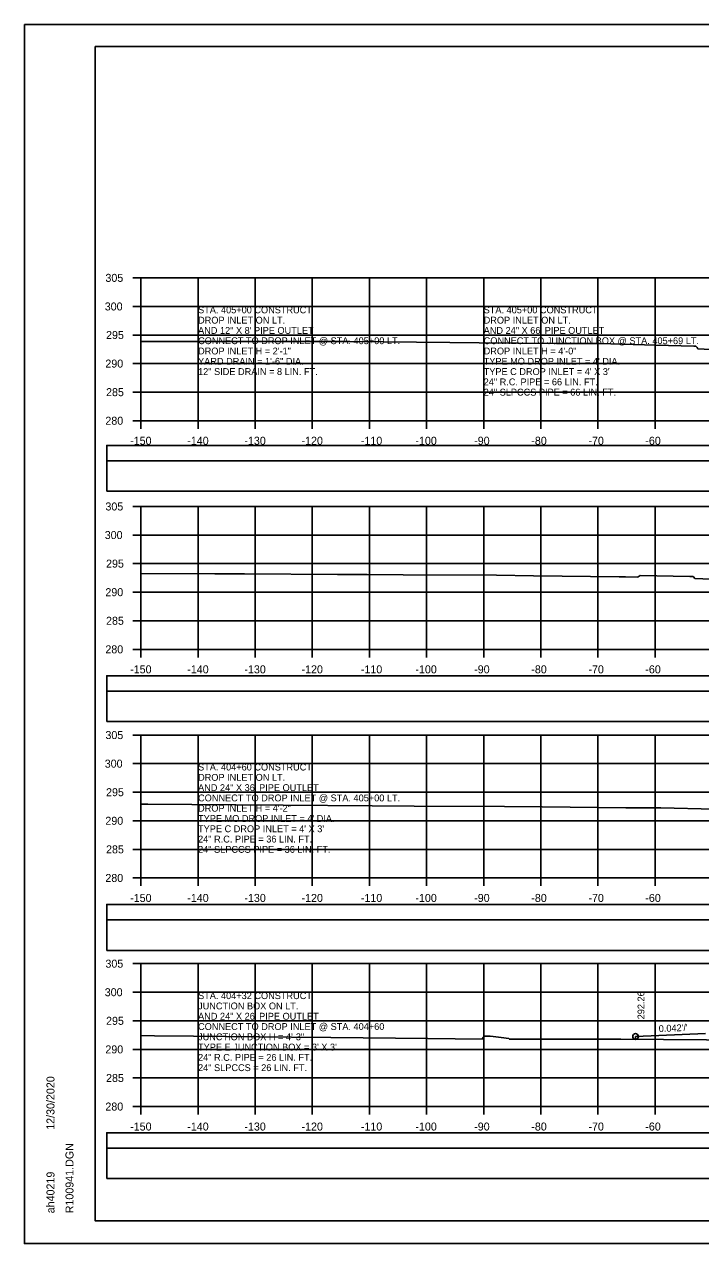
# Model space of a CAD drawing. Extents: x 1370538 to 1372872, y 376220 to 381127.
# Drawn here: x 1370538.2 to 1370656.6, y 376860.4 to 377073.8 of the extents above; entities that cross this region are included whole.
import ezdxf

# ---------------------------------------------------------------- set-up
doc = ezdxf.new("R2010")
doc.units = 0
for name, color, linetype in [('R_Border Notes', 7, 'Continuous'), ('R_Border PE', 7, 'Continuous'), ('R_Border Prem', 7, 'Continuous'), ('R_Dimension', 7, 'Continuous'), ('R_Fin Surface', 7, 'Continuous'), ('R_Grid', 7, 'Continuous'), ('R_No Plot', 7, 'Continuous'), ('R_Water Annot', 7, 'Continuous'), ('R_Xsect Elev', 7, 'Continuous'), ('R_Xsect Slope', 7, 'Continuous'), ('T_Detection Zones', 7, 'Continuous')]:
    doc.layers.add(name, color=color, linetype=linetype)

msp = doc.modelspace()

# ---------------------------------------------------------------- linework, layer by layer
at = {"layer": 'R_Border Notes'}
for p, q in [((1370550.61, 377069.89), (1370866.79, 377069.89)), ((1370550.61, 376864.43), (1370550.61, 377069.89)), ((1370550.61, 376864.43), (1370550.61, 376864.43)), ((1370866.79, 376864.43), (1370550.61, 376864.43))]:
    msp.add_line(p, q, dxfattribs=at)
at = {"layer": 'R_Border Prem'}
for p, q in [((1370557.21, 377029.43), (1370558.61, 377029.43)), ((1370558.61, 377004.43), (1370558.61, 377029.43)), ((1370557.21, 377024.43), (1370558.61, 377024.43)), ((1370557.21, 377019.43), (1370558.61, 377019.43)), ((1370557.21, 377014.43), (1370558.61, 377014.43)), ((1370557.21, 377009.43), (1370558.61, 377009.43)), ((1370557.21, 377004.43), (1370558.61, 377004.43)), ((1370558.61, 377004.43), (1370858.61, 377004.43)), ((1370558.61, 377003.03), (1370558.61, 377004.43)), ((1370568.61, 377003.03), (1370568.61, 377004.43)), ((1370578.61, 377003.03), (1370578.61, 377004.43)), ((1370588.61, 377003.03), (1370588.61, 377004.43)), ((1370598.61, 377003.03), (1370598.61, 377004.43)), ((1370608.61, 377003.03), (1370608.61, 377004.43)), ((1370618.61, 377003.03), (1370618.61, 377004.43)), ((1370628.61, 377003.03), (1370628.61, 377004.43)), ((1370638.61, 377003.03), (1370638.61, 377004.43)), ((1370648.61, 377003.03), (1370648.61, 377004.43)), ((1370557.21, 376989.43), (1370558.61, 376989.43)), ((1370558.61, 376964.43), (1370558.61, 376989.43)), ((1370557.21, 376984.43), (1370558.61, 376984.43)), ((1370557.21, 376979.43), (1370558.61, 376979.43)), ((1370557.21, 376974.43), (1370558.61, 376974.43)), ((1370557.21, 376969.43), (1370558.61, 376969.43)), ((1370557.21, 376964.43), (1370558.61, 376964.43)), ((1370558.61, 376964.43), (1370858.61, 376964.43)), ((1370558.61, 376963.03), (1370558.61, 376964.43)), ((1370568.61, 376963.03), (1370568.61, 376964.43)), ((1370578.61, 376963.03), (1370578.61, 376964.43)), ((1370588.61, 376963.03), (1370588.61, 376964.43)), ((1370598.61, 376963.03), (1370598.61, 376964.43)), ((1370608.61, 376963.03), (1370608.61, 376964.43)), ((1370618.61, 376963.03), (1370618.61, 376964.43)), ((1370628.61, 376963.03), (1370628.61, 376964.43)), ((1370638.61, 376963.03), (1370638.61, 376964.43)), ((1370648.61, 376963.03), (1370648.61, 376964.43)), ((1370557.21, 376949.43), (1370558.61, 376949.43)), ((1370558.61, 376924.43), (1370558.61, 376949.43)), ((1370557.21, 376944.43), (1370558.61, 376944.43)), ((1370557.21, 376939.43), (1370558.61, 376939.43)), ((1370557.21, 376934.43), (1370558.61, 376934.43)), ((1370557.21, 376929.43), (1370558.61, 376929.43)), ((1370557.21, 376924.43), (1370558.61, 376924.43)), ((1370558.61, 376924.43), (1370858.61, 376924.43)), ((1370558.61, 376923.03), (1370558.61, 376924.43)), ((1370568.61, 376923.03), (1370568.61, 376924.43)), ((1370578.61, 376923.03), (1370578.61, 376924.43)), ((1370588.61, 376923.03), (1370588.61, 376924.43)), ((1370598.61, 376923.03), (1370598.61, 376924.43)), ((1370608.61, 376923.03), (1370608.61, 376924.43)), ((1370618.61, 376923.03), (1370618.61, 376924.43)), ((1370628.61, 376923.03), (1370628.61, 376924.43)), ((1370638.61, 376923.03), (1370638.61, 376924.43)), ((1370648.61, 376923.03), (1370648.61, 376924.43)), ((1370557.21, 376909.43), (1370558.61, 376909.43)), ((1370558.61, 376884.43), (1370558.61, 376909.43)), ((1370557.21, 376904.43), (1370558.61, 376904.43)), ((1370557.21, 376899.43), (1370558.61, 376899.43)), ((1370557.21, 376894.43), (1370558.61, 376894.43)), ((1370557.21, 376889.43), (1370558.61, 376889.43)), ((1370557.21, 376884.43), (1370558.61, 376884.43)), ((1370558.61, 376884.43), (1370858.61, 376884.43)), ((1370558.61, 376883.03), (1370558.61, 376884.43)), ((1370568.61, 376883.03), (1370568.61, 376884.43)), ((1370578.61, 376883.03), (1370578.61, 376884.43)), ((1370588.61, 376883.03), (1370588.61, 376884.43)), ((1370598.61, 376883.03), (1370598.61, 376884.43)), ((1370608.61, 376883.03), (1370608.61, 376884.43)), ((1370618.61, 376883.03), (1370618.61, 376884.43)), ((1370628.61, 376883.03), (1370628.61, 376884.43)), ((1370638.61, 376883.03), (1370638.61, 376884.43)), ((1370648.61, 376883.03), (1370648.61, 376884.43))]:
    msp.add_line(p, q, dxfattribs=at)
at = {"layer": 'R_Dimension'}
for points in [[(1370558.61, 377018.28), (1370561.13, 377018.27), (1370568.37, 377018.27), (1370578.14, 377018.27), (1370585.41, 377018.27), (1370595.15, 377018.27), (1370600.99, 377018.22), (1370612.67, 377018.1), (1370617.83, 377018.05), (1370631.35, 377017.96), (1370636.56, 377017.94), (1370637.54, 377017.93), (1370637.62, 377017.94), (1370638.9, 377017.93), (1370648.73, 377017.66), (1370655.42, 377017.49), (1370655.61, 377017.49), (1370655.78, 377017.47), (1370655.99, 377017.22), (1370656.11, 377017.04), (1370670.38, 377016.24)], [(1370558.61, 376977.72), (1370571.56, 376977.66), (1370576.75, 376977.65), (1370593.01, 376977.54), (1370598.22, 376977.54), (1370604.53, 376977.48), (1370620.88, 376977.38), (1370627.32, 376977.32), (1370642.35, 376977.12), (1370643.43, 376977.1), (1370645.62, 376977.06), (1370645.68, 376977.12), (1370645.98, 376977.34), (1370654.72, 376977.19), (1370655.28, 376977.16), (1370655.33, 376977.11), (1370655.6, 376976.83), (1370661.11, 376976.57)], [(1370558.61, 376937.32), (1370559.81, 376937.31), (1370575.24, 376937.24), (1370583.51, 376937.15), (1370599.09, 376937.05), (1370606.43, 376937), (1370622.23, 376936.91), (1370628.86, 376936.87), (1370643.51, 376936.7), (1370649.61, 376936.67), (1370659.03, 376936.49)], [(1370558.61, 376896.85), (1370560.98, 376896.82), (1370567.8, 376896.75), (1370584.98, 376896.57), (1370591.83, 376896.5), (1370608.85, 376896.31), (1370613.61, 376896.29), (1370618.35, 376896.24), (1370618.37, 376896.27), (1370618.69, 376896.72), (1370618.87, 376896.72), (1370619.22, 376896.73), (1370619.27, 376896.74), (1370619.73, 376896.73), (1370620.25, 376896.7), (1370621.65, 376896.52), (1370622.99, 376896.36), (1370623.12, 376896.2), (1370623.27, 376896.2), (1370625.41, 376896.21), (1370642.65, 376896.21), (1370665.12, 376896.06)]]:
    msp.add_lwpolyline(points, dxfattribs=at)
at = {"layer": 'R_Fin Surface'}
msp.add_line((1370645.2, 376896.69), (1370645.2, 376896.19), dxfattribs=at)
msp.add_lwpolyline([(1370645.2, 376896.69), (1370657.42, 376897.21)], dxfattribs=at)
at = {"layer": 'R_Grid'}
for p, q in [((1370558.61, 377029.43), (1370858.61, 377029.43)), ((1370558.61, 377004.43), (1370558.61, 377029.43)), ((1370568.61, 377004.43), (1370568.61, 377029.43)), ((1370578.61, 377004.43), (1370578.61, 377029.43)), ((1370588.61, 377004.43), (1370588.61, 377029.43)), ((1370598.61, 377004.43), (1370598.61, 377029.43)), ((1370608.61, 377004.43), (1370608.61, 377029.43)), ((1370618.61, 377004.43), (1370618.61, 377029.43)), ((1370628.61, 377004.43), (1370628.61, 377029.43)), ((1370638.61, 377004.43), (1370638.61, 377029.43)), ((1370648.61, 377004.43), (1370648.61, 377029.43)), ((1370558.61, 377024.43), (1370858.61, 377024.43)), ((1370558.61, 377019.43), (1370858.61, 377019.43)), ((1370558.61, 377014.43), (1370858.61, 377014.43)), ((1370558.61, 377009.43), (1370858.61, 377009.43)), ((1370558.61, 377004.43), (1370858.61, 377004.43)), ((1370558.61, 376989.43), (1370858.61, 376989.43)), ((1370558.61, 376964.43), (1370558.61, 376989.43)), ((1370568.61, 376964.43), (1370568.61, 376989.43)), ((1370578.61, 376964.43), (1370578.61, 376989.43)), ((1370588.61, 376964.43), (1370588.61, 376989.43)), ((1370598.61, 376964.43), (1370598.61, 376989.43)), ((1370608.61, 376964.43), (1370608.61, 376989.43)), ((1370618.61, 376964.43), (1370618.61, 376989.43)), ((1370628.61, 376964.43), (1370628.61, 376989.43)), ((1370638.61, 376964.43), (1370638.61, 376989.43)), ((1370648.61, 376964.43), (1370648.61, 376989.43)), ((1370558.61, 376984.43), (1370858.61, 376984.43)), ((1370558.61, 376979.43), (1370858.61, 376979.43)), ((1370558.61, 376974.43), (1370858.61, 376974.43)), ((1370558.61, 376969.43), (1370858.61, 376969.43)), ((1370558.61, 376964.43), (1370858.61, 376964.43)), ((1370558.61, 376949.43), (1370858.61, 376949.43)), ((1370558.61, 376924.43), (1370558.61, 376949.43)), ((1370568.61, 376924.43), (1370568.61, 376949.43)), ((1370578.61, 376924.43), (1370578.61, 376949.43)), ((1370588.61, 376924.43), (1370588.61, 376949.43)), ((1370598.61, 376924.43), (1370598.61, 376949.43)), ((1370608.61, 376924.43), (1370608.61, 376949.43)), ((1370618.61, 376924.43), (1370618.61, 376949.43)), ((1370628.61, 376924.43), (1370628.61, 376949.43)), ((1370638.61, 376924.43), (1370638.61, 376949.43)), ((1370648.61, 376924.43), (1370648.61, 376949.43)), ((1370558.61, 376944.43), (1370858.61, 376944.43)), ((1370558.61, 376939.43), (1370858.61, 376939.43)), ((1370558.61, 376934.43), (1370858.61, 376934.43)), ((1370558.61, 376929.43), (1370858.61, 376929.43)), ((1370558.61, 376924.43), (1370858.61, 376924.43)), ((1370558.61, 376909.43), (1370858.61, 376909.43)), ((1370558.61, 376884.43), (1370558.61, 376909.43)), ((1370568.61, 376884.43), (1370568.61, 376909.43)), ((1370578.61, 376884.43), (1370578.61, 376909.43)), ((1370588.61, 376884.43), (1370588.61, 376909.43)), ((1370598.61, 376884.43), (1370598.61, 376909.43)), ((1370608.61, 376884.43), (1370608.61, 376909.43)), ((1370618.61, 376884.43), (1370618.61, 376909.43)), ((1370628.61, 376884.43), (1370628.61, 376909.43)), ((1370638.61, 376884.43), (1370638.61, 376909.43)), ((1370648.61, 376884.43), (1370648.61, 376909.43)), ((1370558.61, 376904.43), (1370858.61, 376904.43)), ((1370558.61, 376899.43), (1370858.61, 376899.43)), ((1370558.61, 376894.43), (1370858.61, 376894.43)), ((1370558.61, 376889.43), (1370858.61, 376889.43)), ((1370558.61, 376884.43), (1370858.61, 376884.43))]:
    msp.add_line(p, q, dxfattribs=at)
at = {"layer": 'R_No Plot'}
for p, q in [((1370538.21, 377073.78), (1370871.54, 377073.78)), ((1370538.21, 376860.45), (1370871.54, 376860.45))]:
    msp.add_line(p, q, dxfattribs=at)
for points in [[(1370538.2, 377073.78), (1370871.54, 377073.78), (1370871.54, 376860.45), (1370538.2, 376860.45)], [(1370784.53, 377069.89), (1370784.53, 377060.01), (1370820.26, 377060.01), (1370820.26, 377057.09), (1370843.46, 377057.09), (1370843.46, 377032.76), (1370866.79, 377032.76), (1370866.79, 376864.43), (1370550.61, 376864.43), (1370550.61, 377069.89)]]:
    msp.add_lwpolyline(points, close=True, dxfattribs=at)
msp.add_circle((1370645.2, 376896.69), 0.5, dxfattribs=at)
at = {"layer": 'T_Detection Zones'}
for points in [[(1370552.62, 376997.42), (1370864.59, 376997.42), (1370864.59, 377000.12), (1370552.62, 377000.12)], [(1370552.62, 376992.1), (1370864.59, 376992.1), (1370864.59, 376997.42), (1370552.62, 376997.42)], [(1370552.62, 376957.1), (1370864.59, 376957.1), (1370864.59, 376959.81), (1370552.62, 376959.81)], [(1370552.62, 376951.78), (1370864.59, 376951.78), (1370864.59, 376957.1), (1370552.62, 376957.1)], [(1370552.62, 376917.09), (1370864.59, 376917.09), (1370864.59, 376919.79), (1370552.62, 376919.79)], [(1370552.62, 376911.76), (1370864.59, 376911.76), (1370864.59, 376917.09), (1370552.62, 376917.09)], [(1370552.62, 376877.15), (1370864.59, 376877.15), (1370864.59, 376879.85), (1370552.62, 376879.85)], [(1370552.62, 376871.82), (1370864.59, 376871.82), (1370864.59, 376877.15), (1370552.62, 376877.15)]]:
    msp.add_lwpolyline(points, close=True, dxfattribs=at)

# ---------------------------------------------------------------- texts
at = {"layer": 'R_Border Notes'}
for s, p in [('12/30/2020', (1370543.47, 376880.36)), ('R100941.DGN', (1370546.8, 376865.75)), ('ah40219', (1370543.47, 376865.75))]:
    msp.add_text(s, height=1.4, rotation=90, dxfattribs=at).set_placement(p)
at = {"layer": 'R_Border PE'}
for s, p in [('305', (1370552.39, 377028.73)), ('300', (1370552.27, 377023.73)), ('295', (1370552.5, 377018.73)), ('290', (1370552.38, 377013.73)), ('285', (1370552.5, 377008.73)), ('280', (1370552.38, 377003.73)), ('-150', (1370556.72, 377000.23)), ('-140', (1370566.72, 377000.23)), ('-130', (1370576.72, 377000.23)), ('-120', (1370586.72, 377000.23)), ('-110', (1370597.11, 377000.23)), ('-100', (1370606.66, 377000.23)), ('-90', (1370616.95, 377000.23)), ('-80', (1370626.95, 377000.23)), ('-70', (1370636.95, 377000.23)), ('-60', (1370646.91, 377000.23)), ('305', (1370552.39, 376988.73)), ('300', (1370552.27, 376983.73)), ('295', (1370552.5, 376978.73)), ('290', (1370552.38, 376973.73)), ('285', (1370552.5, 376968.73)), ('280', (1370552.38, 376963.73)), ('-150', (1370556.72, 376960.23)), ('-140', (1370566.72, 376960.23)), ('-130', (1370576.72, 376960.23)), ('-120', (1370586.72, 376960.23)), ('-110', (1370597.11, 376960.23)), ('-100', (1370606.66, 376960.23)), ('-90', (1370616.95, 376960.23)), ('-80', (1370626.95, 376960.23)), ('-70', (1370636.95, 376960.23)), ('-60', (1370646.91, 376960.23)), ('305', (1370552.39, 376948.73)), ('300', (1370552.27, 376943.73)), ('295', (1370552.5, 376938.73)), ('290', (1370552.38, 376933.73)), ('285', (1370552.5, 376928.73)), ('280', (1370552.38, 376923.73)), ('-150', (1370556.72, 376920.23)), ('-140', (1370566.72, 376920.23)), ('-130', (1370576.72, 376920.23)), ('-120', (1370586.72, 376920.23)), ('-110', (1370597.11, 376920.23)), ('-100', (1370606.66, 376920.23)), ('-90', (1370616.95, 376920.23)), ('-80', (1370626.95, 376920.23)), ('-70', (1370636.95, 376920.23)), ('-60', (1370646.91, 376920.23)), ('305', (1370552.39, 376908.73)), ('300', (1370552.27, 376903.73)), ('295', (1370552.5, 376898.73)), ('290', (1370552.38, 376893.73)), ('285', (1370552.5, 376888.73)), ('280', (1370552.38, 376883.73)), ('-150', (1370556.72, 376880.23)), ('-140', (1370566.72, 376880.23)), ('-130', (1370576.72, 376880.23)), ('-120', (1370586.72, 376880.23)), ('-110', (1370597.11, 376880.23)), ('-100', (1370606.66, 376880.23)), ('-90', (1370616.95, 376880.23)), ('-80', (1370626.95, 376880.23)), ('-70', (1370636.95, 376880.23)), ('-60', (1370646.91, 376880.23))]:
    msp.add_text(s, height=1.4, dxfattribs=at).set_placement(p)
at = {"layer": 'R_Water Annot'}
for s, p in [('STA. 405+00 CONSTRUCT', (1370568.61, 377023.23)), ('STA. 405+00 CONSTRUCT', (1370618.61, 377023.23)), ('DROP INLET ON LT.', (1370568.61, 377021.43)), ('DROP INLET ON LT.', (1370618.61, 377021.43)), ('AND 12" X 8\' PIPE OUTLET', (1370568.61, 377019.63)), ('CONNECT TO DROP INLET @ STA. 405+00 LT.', (1370568.61, 377017.83)), ('AND 24" X 66\' PIPE OUTLET', (1370618.61, 377019.63)), ('CONNECT TO JUNCTION BOX @ STA. 405+69 LT.', (1370618.61, 377017.83)), ('DROP INLET H = 2\'-1"', (1370568.61, 377016.03)), ('DROP INLET H = 4\'-0"', (1370618.61, 377016.03)), ('YARD DRAIN = 1\'-6" DIA.', (1370568.61, 377014.23)), ("TYPE MO DROP INLET = 4' DIA.", (1370618.61, 377014.23)), ('12" SIDE DRAIN = 8 LIN. FT.', (1370568.61, 377012.43)), ("TYPE C DROP INLET = 4' X 3'", (1370618.61, 377012.43)), ('24" R.C. PIPE = 66 LIN. FT.', (1370618.61, 377010.63)), ('24" SLPCCS PIPE = 66 LIN. FT.', (1370618.61, 377008.83)), ('STA. 404+60 CONSTRUCT', (1370568.61, 376943.23)), ('DROP INLET ON LT.', (1370568.61, 376941.43)), ('AND 24" X 36\' PIPE OUTLET', (1370568.61, 376939.63)), ('CONNECT TO DROP INLET @ STA. 405+00 LT.', (1370568.61, 376937.83)), ('DROP INLET H = 4\'-2"', (1370568.61, 376936.03)), ("TYPE MO DROP INLET = 4' DIA.", (1370568.61, 376934.23)), ("TYPE C DROP INLET = 4' X 3'", (1370568.61, 376932.43)), ('24" R.C. PIPE = 36 LIN. FT.', (1370568.61, 376930.63)), ('24" SLPCCS PIPE = 36 LIN. FT.', (1370568.61, 376928.83)), ('STA. 404+32 CONSTRUCT', (1370568.61, 376903.23)), ('JUNCTION BOX ON LT.', (1370568.61, 376901.43)), ('AND 24" X 26\' PIPE OUTLET', (1370568.61, 376899.63)), ('JUNCTION BOX H = 4\'-3"', (1370568.61, 376896.03)), ('CONNECT TO DROP INLET @ STA. 404+60', (1370568.61, 376897.83)), ("TYPE E JUNCTION BOX = 3' X 3'", (1370568.61, 376894.23)), ('24" R.C. PIPE = 26 LIN. FT.', (1370568.61, 376892.43)), ('24" SLPCCS = 26 LIN. FT.', (1370568.61, 376890.63))]:
    msp.add_text(s, height=1.2, dxfattribs=at).set_placement(p)
at = {"layer": 'R_Xsect Elev'}
msp.add_text('292.26', height=1.2, rotation=90, dxfattribs=at).set_placement((1370646.75, 376899.69))
at = {"layer": 'R_Xsect Slope'}
msp.add_text("0.042'/'", height=1.2, rotation=2.3871, dxfattribs=at).set_placement((1370649.28, 376897.46))

doc.saveas('drawing.dxf')
